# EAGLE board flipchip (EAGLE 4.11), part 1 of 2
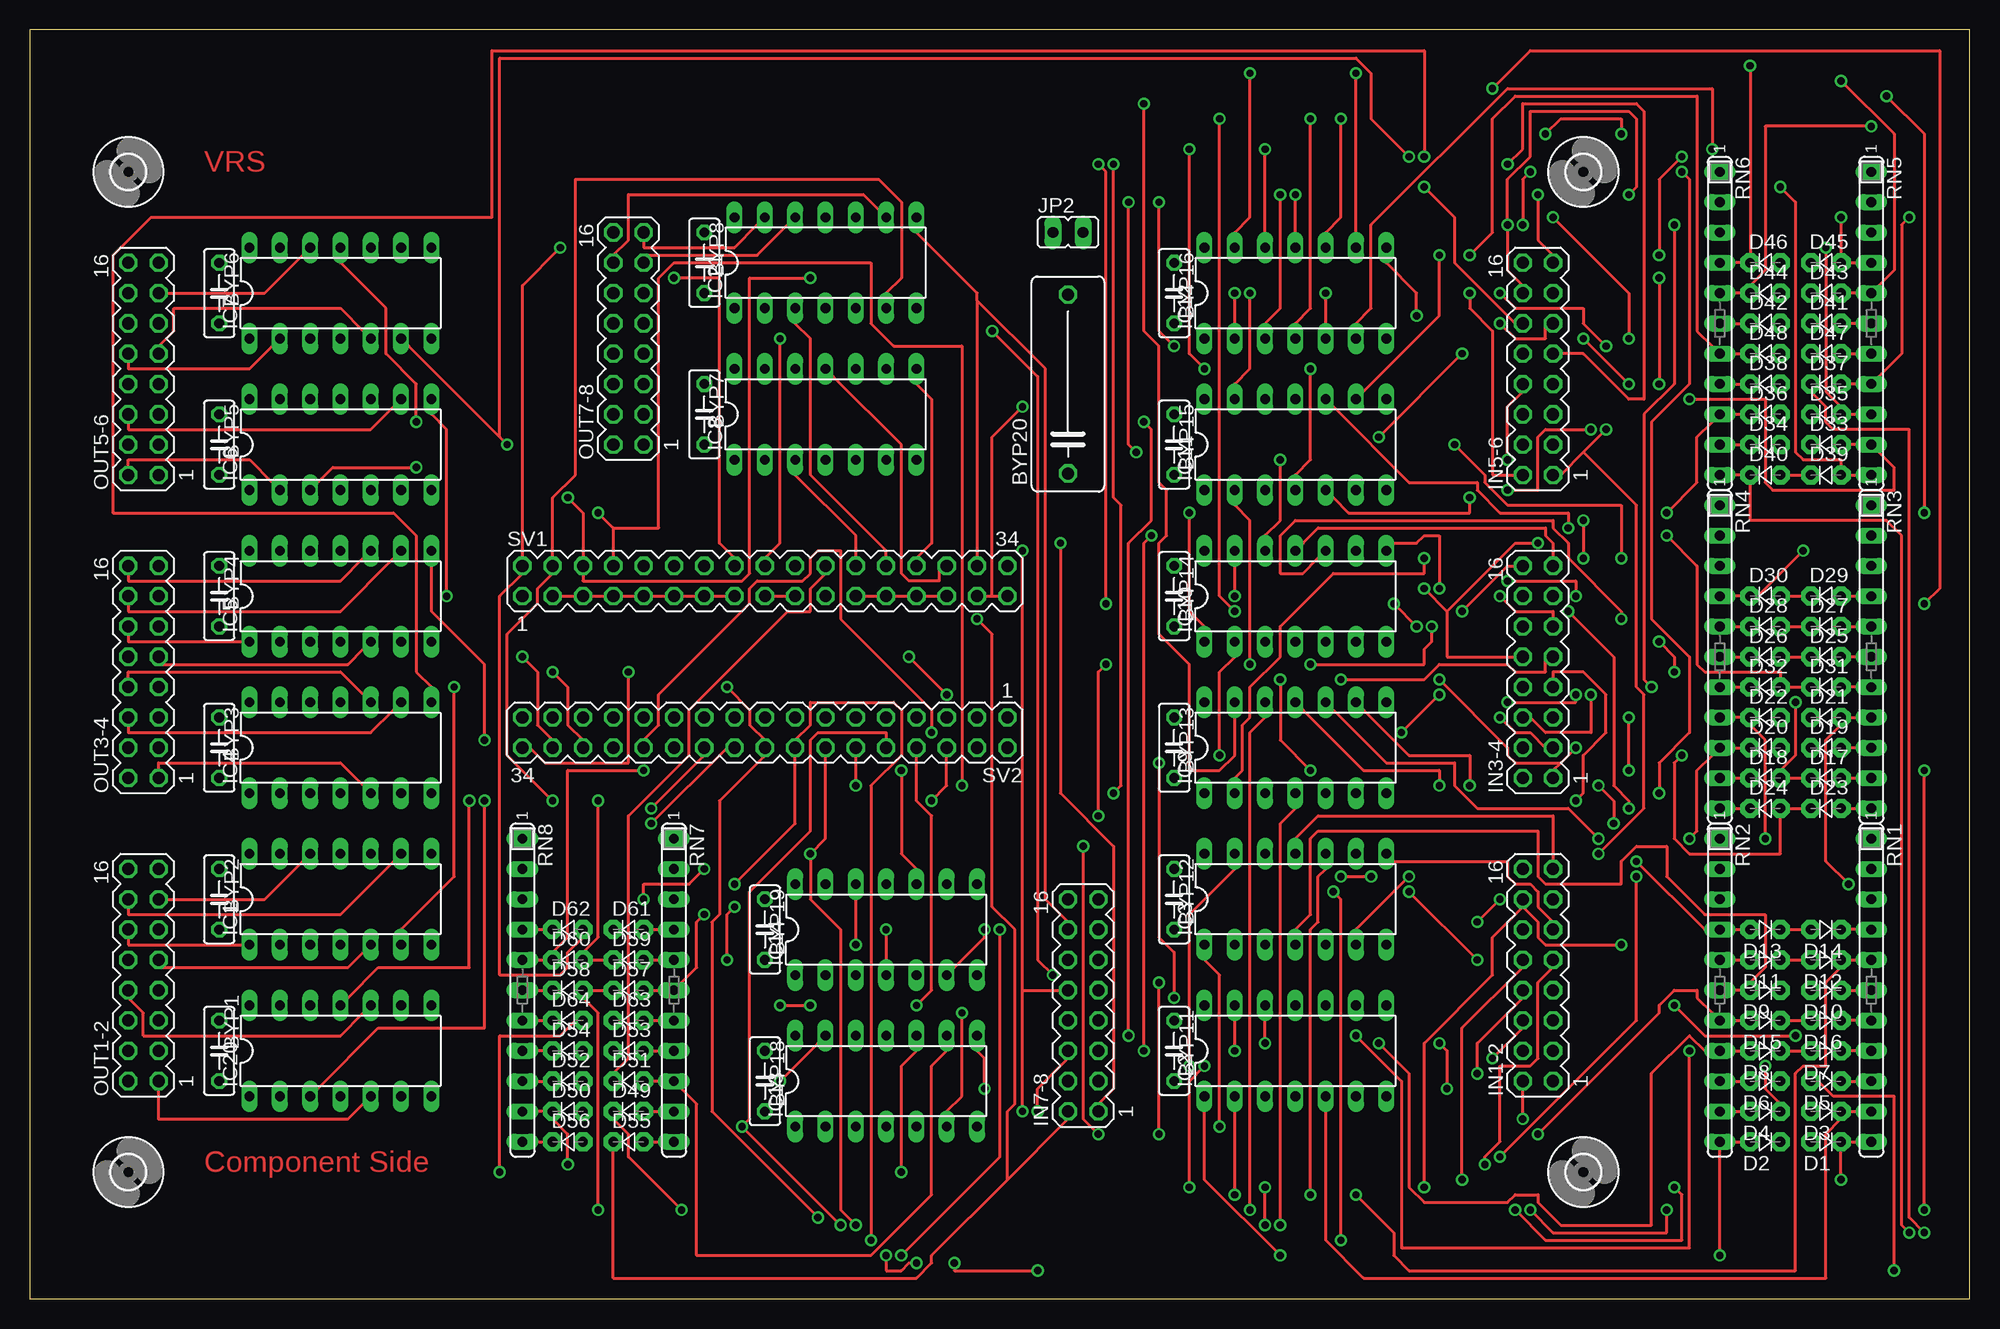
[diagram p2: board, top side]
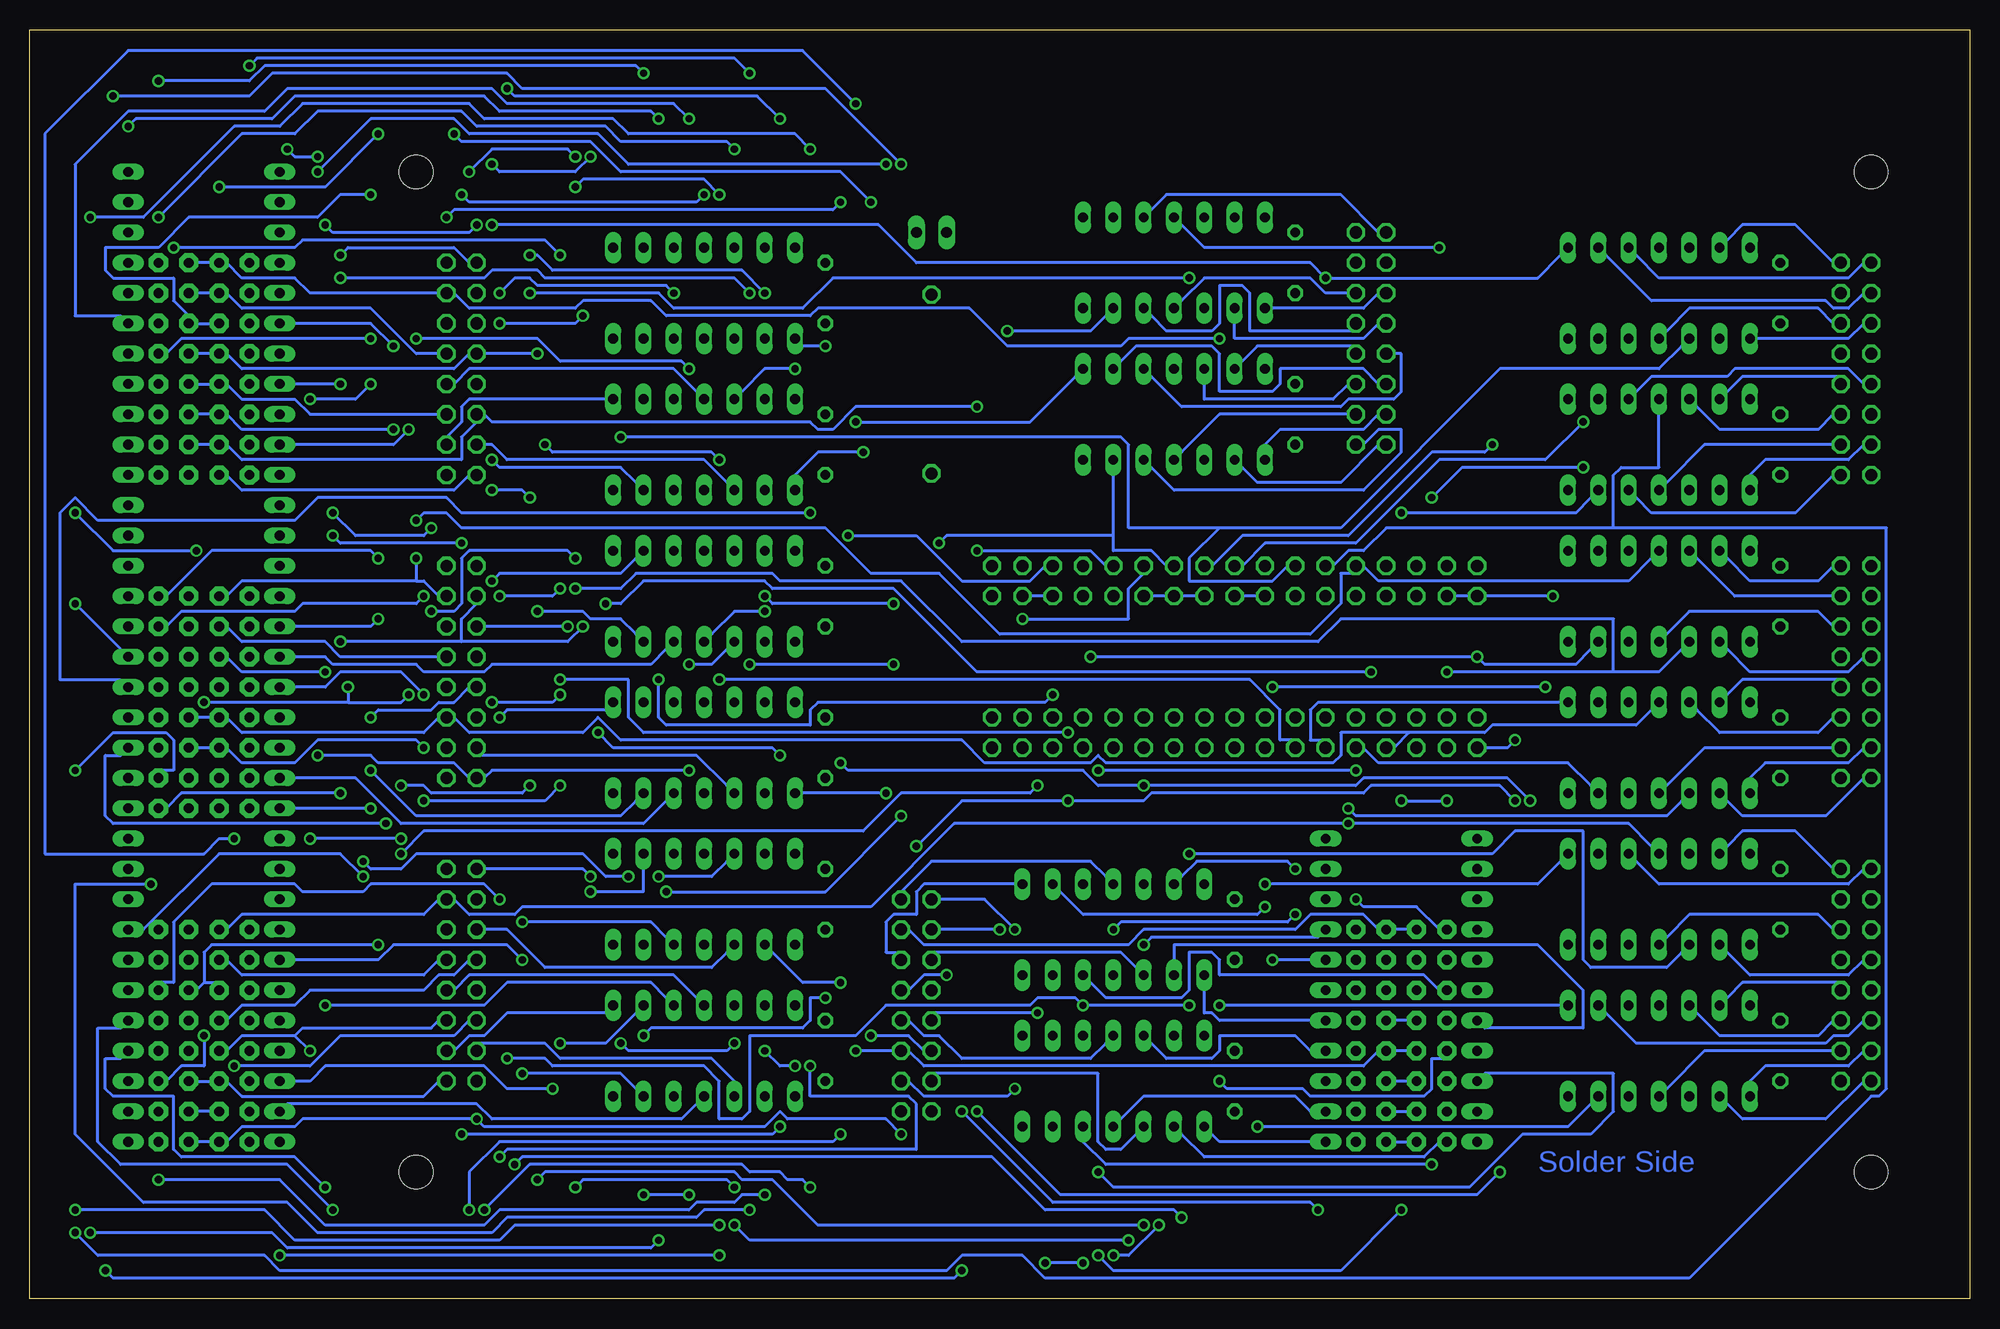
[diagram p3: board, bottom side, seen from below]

Size 162.54 x 106.35 mm. Coordinates in mm from the lower left corner, seen from the top.
Outline: 0,0 162.54,0 162.54,106.35 0,106.35 0,0
Copper layers (1*16): Top 0.035mm / dielectric 1.5mm / Bottom 0.035mm
Design rules "olimex10mil": minimum track width 10mil, minimum drill 24mil, track to track 10mil, track to pad 10mil, pad to pad 10mil, via to via 10mil, smd to smd 10mil, copper to edge 40mil, drill to drill 10mil, minimum pad ring 10mil, minimum via ring 8mil, stop-mask expansion 0mil, vias tented up to drill 0mil, thermal gap 10mil
Net classes: 1 Power: width 0.508 mm, drill 0.254 mm, clearance 0.254 mm

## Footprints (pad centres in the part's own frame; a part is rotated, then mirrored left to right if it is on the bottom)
C050-025X075 = drill 0.813 octagon: 1 -2.54,0; 2 2.54,0
C150-064X183 = drill 1.016 octagon: 1 -7.493,0; 2 7.493,0
D-2,5 = drill 0.813 pad 1.6 octagon: 1 -1.27,0; 2 1.27,0
DIL14 = drill 0.813 long: 1 -7.62,-3.81; 2 -5.08,-3.81; 3 -2.54,-3.81; 4 0,-3.81; 5 2.54,-3.81; 6 5.08,-3.81; 7 7.62,-3.81; 8 7.62,3.81; 9 5.08,3.81; 10 2.54,3.81; 11 0,3.81; 12 -2.54,3.81; 13 -5.08,3.81; 14 -7.62,3.81
MA08-2 = drill 1.016 octagon: 1 -8.89,-1.27; 2 -8.89,1.27; 3 -6.35,-1.27; 4 -6.35,1.27; 5 -3.81,-1.27; 6 -3.81,1.27; 7 -1.27,-1.27; 8 -1.27,1.27; 9 1.27,-1.27; 10 1.27,1.27; 11 3.81,-1.27; 12 3.81,1.27; 13 6.35,-1.27; 14 6.35,1.27; 15 8.89,-1.27; 16 8.89,1.27
JP1 = drill 0.914 long: 1 0,-1.27; 2 0,1.27
SIL11 = drill 0.813 long: 1 -12.7,0; 2 -10.16,0; 3 -7.62,0; 4 -5.08,0; 5 -2.54,0; 6 0,0; 7 2.54,0; 8 5.08,0; 9 7.62,0; 10 10.16,0; 11 12.7,0
MA17-2 = drill 1.016 octagon: 1 -20.32,-1.27; 2 -20.32,1.27; 3 -17.78,-1.27; 4 -17.78,1.27; 5 -15.24,-1.27; 6 -15.24,1.27; 7 -12.7,-1.27; 8 -12.7,1.27; 9 -10.16,-1.27; 10 -10.16,1.27; 11 -7.62,-1.27; 12 -7.62,1.27; 13 -5.08,-1.27; 14 -5.08,1.27; 15 -2.54,-1.27; 16 -2.54,1.27; 17 0,-1.27; 18 0,1.27; 19 2.54,-1.27; 20 2.54,1.27; 21 5.08,-1.27; 22 5.08,1.27; 23 7.62,-1.27; 24 7.62,1.27; 25 10.16,-1.27; 26 10.16,1.27; 27 12.7,-1.27; 28 12.7,1.27; 29 15.24,-1.27; 30 15.24,1.27; 31 17.78,-1.27; 32 17.78,1.27; 33 20.32,-1.27; 34 20.32,1.27
2,8 = hole 2.8: 0,0

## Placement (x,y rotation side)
BYP1  0.1uf  [C050-025X075]  15.87,20.79 270 top
BYP2  0.1uf  [C050-025X075]  15.87,33.49 270 top
BYP3  0.1uf  [C050-025X075]  15.87,46.19 270 top
BYP4  0.1uf  [C050-025X075]  15.87,58.89 270 top
BYP5  0.1uf  [C050-025X075]  15.87,71.59 270 top
BYP6  0.1uf  [C050-025X075]  15.87,84.29 270 top
BYP7  0.1uf  [C050-025X075]  56.51,74.13 270 top
BYP8  0.1uf  [C050-025X075]  56.51,86.83 270 top
BYP11  0.1uf  [C050-025X075]  95.88,20.79 270 top
BYP12  0.1uf  [C050-025X075]  95.88,33.49 270 top
BYP13  0.1uf  [C050-025X075]  95.88,46.19 270 top
BYP14  0.1uf  [C050-025X075]  95.88,58.89 270 top
BYP15  0.1uf  [C050-025X075]  95.88,71.59 270 top
BYP16  0.1uf  [C050-025X075]  95.88,84.29 270 top
BYP18  0.1uf  [C050-025X075]  61.59,18.25 270 top
BYP19  0.1uf  [C050-025X075]  61.59,30.95 270 top
BYP20  100uf 25V  [C150-064X183]  86.99,76.67 90 top
D1  [D-2,5]  150.49,13.17 0 top
D2  [D-2,5]  145.41,13.17 0 top
D3  [D-2,5]  150.49,15.71 0 top
D4  [D-2,5]  145.41,15.71 0 top
D5  [D-2,5]  150.49,18.25 0 top
D6  [D-2,5]  145.41,18.25 0 top
D7  [D-2,5]  150.49,20.79 0 top
D8  [D-2,5]  145.41,20.79 0 top
D9  [D-2,5]  145.41,25.87 0 top
D10  [D-2,5]  150.49,25.87 0 top
D11  [D-2,5]  145.41,28.41 0 top
D12  [D-2,5]  150.49,28.41 0 top
D13  [D-2,5]  145.41,30.95 0 top
D14  [D-2,5]  150.49,30.95 0 top
D15  [D-2,5]  145.41,23.33 0 top
D16  [D-2,5]  150.49,23.33 0 top
D17  [D-2,5]  150.49,43.65 180 top
D18  [D-2,5]  145.41,43.65 180 top
D19  [D-2,5]  150.49,46.19 180 top
D20  [D-2,5]  145.41,46.19 180 top
D21  [D-2,5]  150.49,48.73 180 top
D22  [D-2,5]  145.41,48.73 180 top
D23  [D-2,5]  150.49,41.11 180 top
D24  [D-2,5]  145.41,41.11 180 top
D25  [D-2,5]  150.49,53.81 180 top
D26  [D-2,5]  145.41,53.81 180 top
D27  [D-2,5]  150.49,56.35 180 top
D28  [D-2,5]  145.41,56.35 180 top
D29  [D-2,5]  150.49,58.89 180 top
D30  [D-2,5]  145.41,58.89 180 top
D31  [D-2,5]  150.49,51.27 180 top
D32  [D-2,5]  145.41,51.27 180 top
D33  [D-2,5]  150.49,71.59 180 top
D34  [D-2,5]  145.41,71.59 180 top
D35  [D-2,5]  150.49,74.13 180 top
D36  [D-2,5]  145.41,74.13 180 top
D37  [D-2,5]  150.49,76.67 180 top
D38  [D-2,5]  145.41,76.67 180 top
D39  [D-2,5]  150.49,69.05 180 top
D40  [D-2,5]  145.41,69.05 180 top
D41  [D-2,5]  150.49,81.75 180 top
D42  [D-2,5]  145.41,81.75 180 top
D43  [D-2,5]  150.49,84.29 180 top
D44  [D-2,5]  145.41,84.29 180 top
D45  [D-2,5]  150.49,86.83 180 top
D46  [D-2,5]  145.41,86.83 180 top
D47  [D-2,5]  150.49,79.21 180 top
D48  [D-2,5]  145.41,79.21 180 top
D49  [D-2,5]  50.16,15.71 180 top
D50  [D-2,5]  45.08,15.71 180 top
D51  [D-2,5]  50.16,18.25 180 top
D52  [D-2,5]  45.08,18.25 180 top
D53  [D-2,5]  50.16,20.79 180 top
D54  [D-2,5]  45.08,20.79 180 top
D55  [D-2,5]  50.16,13.17 180 top
D56  [D-2,5]  45.08,13.17 180 top
D57  [D-2,5]  50.16,25.87 180 top
D58  [D-2,5]  45.08,25.87 180 top
D59  [D-2,5]  50.16,28.41 180 top
D60  [D-2,5]  45.08,28.41 180 top
D61  [D-2,5]  50.16,30.95 180 top
D62  [D-2,5]  45.08,30.95 180 top
D63  [D-2,5]  50.16,23.33 180 top
D64  [D-2,5]  45.08,23.33 180 top
IC1  74LS125N  [DIL14]  26.03,33.49 0 top
IC2  74HCT86N  [DIL14]  106.04,20.79 0 top
IC3  74HCT86N  [DIL14]  106.04,33.49 0 top
IC4  74LS125N  [DIL14]  26.03,46.19 0 top
IC5  74LS125N  [DIL14]  26.03,58.89 0 top
IC6  74LS125N  [DIL14]  26.03,71.59 0 top
IC7  74LS125N  [DIL14]  26.03,84.29 0 top
IC8  74LS125N  [DIL14]  66.67,74.13 0 top
IC9  74HCT86N  [DIL14]  106.04,46.19 0 top
IC10  74HCT86N  [DIL14]  106.04,58.89 0 top
IC11  74HCT86N  [DIL14]  106.04,71.59 0 top
IC12  74HCT86N  [DIL14]  106.04,84.29 0 top
IC13  74HCT86N  [DIL14]  71.75,18.25 0 top
IC14  74HCT86N  [DIL14]  71.75,30.95 0 top
IC20  74LS125N  [DIL14]  26.03,20.79 0 top
IC21  74LS125N  [DIL14]  66.67,86.83 0 top
IN1-2  [MA08-2]  126.36,27.14 90 top
IN3-4  [MA08-2]  126.36,52.54 90 top
IN5-6  [MA08-2]  126.36,77.94 90 top
IN7-8  [MA08-2]  88.26,24.6 90 top
JP2  POWER  [JP1]  86.99,89.37 270 top
OUT1-2  [MA08-2]  9.52,27.14 90 top
OUT3-4  [MA08-2]  9.52,52.54 90 top
OUT5-6  [MA08-2]  9.52,77.94 90 top
OUT7-8  [MA08-2]  50.16,80.48 90 top
RN1  [SIL11]  154.3,25.87 270 top
RN2  [SIL11]  141.6,25.87 270 top
RN3  [SIL11]  154.3,53.81 270 top
RN4  [SIL11]  141.6,53.81 270 top
RN5  [SIL11]  154.3,81.75 270 top
RN6  [SIL11]  141.6,81.75 270 top
RN7  [SIL11]  53.97,25.87 270 top
RN8  [SIL11]  41.27,25.87 270 top
SV1  [MA17-2]  61.59,60.16 0 top
SV2  [MA17-2]  61.59,47.46 180 top
U$1  [2,8]  130.17,10.63 0 top
U$2  [2,8]  130.17,94.45 0 top
U$3  [2,8]  8.25,94.45 0 top
U$4  [2,8]  8.25,10.63 0 top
